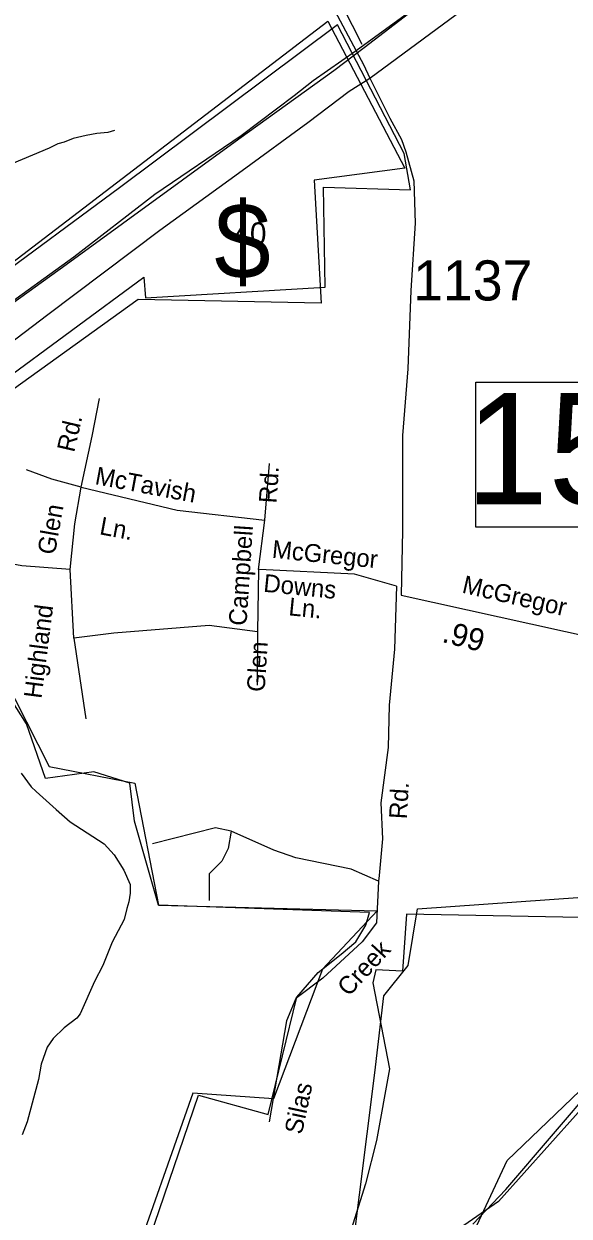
# Model space of a CAD drawing. Extents: x 1551653 to 1702041, y 811336 to 920032.
# Drawn here: x 1597078 to 1599087, y 836287 to 840677 of the extents above; entities that cross this region are included whole.
import ezdxf

# ---------------------------------------------------------------- set-up
doc = ezdxf.new("R2010")
doc.units = 0
for name, color, linetype in [('Old_Level_10', 7, 'Continuous'), ('Old_Level_11', 7, 'Continuous'), ('Old_Level_17', 7, 'Continuous'), ('Old_Level_27', 7, 'Continuous'), ('Old_Level_3', 7, 'Continuous'), ('Old_Level_31', 7, 'Continuous'), ('Old_Level_32', 7, 'Continuous'), ('Old_Level_35', 7, 'Continuous'), ('Old_Level_48', 7, 'Continuous'), ('Old_Level_49', 7, 'Continuous'), ('Old_Level_5', 7, 'Continuous'), ('Old_Level_50', 7, 'Continuous'), ('Old_Level_59', 7, 'Continuous'), ('Old_Level_62', 7, 'Continuous'), ('Old_Level_8', 7, 'Continuous')]:
    doc.layers.add(name, color=color, linetype=linetype)

msp = doc.modelspace()

# ---------------------------------------------------------------- linework, layer by layer
at = {"layer": 'Old_Level_27'}
for points in [[(1603749.199, 844559.05), (1603350.936, 844269.724), (1602985.407, 844007.693), (1602205.248, 843461.795), (1601812.441, 843177.929), (1600912.848, 842516.121), (1600254.489, 842037.883), (1599906.488, 841775.814), (1599790.188, 841685.644), (1598872.668, 840996.696), (1598523.52, 840738.735), (1598301.991, 840577.574)], [(1598352.903, 840476.76), (1598647.546, 840694.656), (1598988.5, 840943.574), (1599440.96, 841276.179), (1599818.792, 841557.187)], [(1598301.991, 840577.574), (1598143.564, 840466.869), (1598074.406, 840412.629), (1597878.626, 840264.575), (1597560.758, 840048.849), (1597262.333, 839818.275), (1596982.399, 839616.43), (1596687.022, 839400.03), (1596364.732, 839161.912), (1596107.627, 838970.645), (1596042.383, 838935.89)], [(1596092.911, 838801.101), (1596244.861, 838917.73), (1596486.859, 839105.695), (1596847.309, 839365.195), (1597165.963, 839607.175), (1597579.315, 839916.898), (1597882.302, 840136.824), (1598123.963, 840313.537), (1598276.244, 840429.627), (1598352.903, 840476.76)]]:
    msp.add_lwpolyline(points, dxfattribs=at)
at = {"layer": 'Old_Level_3'}
for points in [[(1598325.033, 840600.719), (1598253.118, 840740.824), (1598180.949, 840880.805), (1598108.584, 841020.691), (1598036.082, 841160.509), (1597963.5, 841300.289), (1597890.896, 841440.059), (1597818.33, 841579.846), (1597745.858, 841719.68), (1597673.539, 841859.588), (1597601.432, 841999.598), (1597529.593, 842139.741), (1597458.083, 842280.042), (1597386.958, 842420.531), (1597316.278, 842561.235), (1597246.098, 842702.184), (1597176.48, 842843.406), (1597107.019, 842984.781)], [(1599820.273, 841684.214), (1599709.545, 841598.913), (1599489.729, 841446.354), (1599029.592, 841109.248), (1598642.454, 840827.917), (1598331.595, 840589.236)], [(1598331.595, 840589.236), (1598220.046, 840503.935), (1597869.817, 840252.951), (1597234.156, 839790.353), (1596609.157, 839340.879), (1596036.652, 838929.135), (1595602.762, 838614.175), (1595303.386, 838389.438), (1594958.078, 838135.993), (1594733.341, 837966.21), (1594619.332, 837875.987), (1594420.841, 837711.125)]]:
    msp.add_lwpolyline(points, dxfattribs=at)
at = {"layer": 'Old_Level_31'}
for p, q in [((1598329.485, 840527.997), (1598329.485, 840527.997)), ((1598276.244, 840429.627), (1598276.244, 840429.627))]:
    msp.add_line(p, q, dxfattribs=at)
msp.add_lwpolyline([(1598743.706, 839357.959), (1599729.662, 839357.959), (1599729.662, 838823.21), (1598743.706, 838823.21), (1598743.706, 839357.959)], dxfattribs=at)
at = {"layer": 'Old_Level_32'}
for points in [[(1597987.228, 843606.896), (1597894.988, 843361.143), (1597859.075, 843253.102), (1597810.548, 843134.213), (1597782.802, 843038.921), (1597771.621, 842971.11), (1597766.982, 842831.327), (1597764.587, 842703.302), (1597759.341, 842533.512), (1597761.595, 842437.413), (1597768.458, 842371.439), (1597791.93, 842240.8), (1597800.122, 842146.869), (1597827.563, 841901.575), (1597863.79, 841596.07), (1597865.276, 841560.692), (1597884.164, 841505.608), (1597917.537, 841355.741), (1597940.118, 841294.755), (1598019.037, 841130.037), (1598087.886, 840990.068), (1598233.756, 840706.175), (1598301.991, 840577.574)], [(1598301.991, 840577.574), (1598329.485, 840527.997), (1598352.903, 840476.76)], [(1598352.903, 840476.76), (1598426.841, 840329.426), (1598469.519, 840251.188), (1598485.184, 840205.54), (1598515.592, 840099.023), (1598519.393, 839943.052), (1598504.189, 839695.78), (1598492.786, 839406.662), (1598473.781, 839161.035), (1598473.912, 838811.655), (1598467.871, 838573.462)], [(1598467.871, 838573.462), (1599190.984, 838413.375), (1599712.283, 838300.454), (1600672.675, 838162.793), (1600909.768, 838111.756), (1601019.889, 838072.308), (1601634.794, 837815.315)]]:
    msp.add_lwpolyline(points, dxfattribs=at)
at = {"layer": 'Old_Level_35'}
for p, q in [((1597966.132, 838849.406), (1597982.964, 839058.294)), ((1597942.566, 838667.472), (1597966.132, 838849.406)), ((1597262.528, 838414.784), (1597249.062, 838667.472)), ((1597942.566, 838667.472), (1597939.2, 838438.369)), ((1597262.528, 838414.784), (1597306.292, 838118.298)), ((1597939.2, 838438.369), (1597937.981, 838242.181))]:
    msp.add_line(p, q, dxfattribs=at)
for points in [[(1597289.46, 838970.696), (1597329.858, 839159.37), (1597356.79, 839297.505)], [(1597289.46, 838970.696), (1597181.731, 839001.019), (1597087.468, 839034.71)], [(1597249.062, 838667.472), (1597265.894, 838835.929), (1597289.46, 838970.696)], [(1597289.46, 838970.696), (1597642.945, 838886.467), (1597966.132, 838849.406)], [(1597249.062, 838667.472), (1597070.635, 838680.949), (1596925.875, 838707.901), (1596821.512, 838751.701), (1596703.684, 838862.883)], [(1598451.106, 838606.23), (1598296.051, 838650.626), (1597945.933, 838667.472)], [(1598451.106, 838606.23), (1598443.505, 838374.175), (1598424.5, 838168.749), (1598420.699, 838012.777), (1598393.077, 837808.614), (1598399.402, 837676.613), (1598387.64, 837540.773), (1598384.715, 837519.503)], [(1597939.2, 838438.369), (1597760.773, 838461.953), (1597410.163, 838433.055), (1597262.528, 838414.784)], [(1597842.473, 837704.379), (1597784.344, 837716.014), (1597551.829, 837657.84)], [(1597842.473, 837704.379), (1597830.848, 837640.387), (1597807.596, 837593.848), (1597761.093, 837547.308), (1597761.093, 837448.412)], [(1598384.715, 837519.503), (1598284.252, 837564.761), (1598080.801, 837605.482), (1597999.421, 837634.569), (1597842.473, 837704.379)], [(1598384.715, 837519.503), (1598377.258, 837366.968), (1598324.942, 837297.159), (1598179.62, 837163.358), (1598080.801, 837087.732), (1598045.924, 837006.287), (1597981.983, 836633.972)]]:
    msp.add_lwpolyline(points, dxfattribs=at)
at = {"layer": 'Old_Level_48'}
for points in [[(1595336.25, 840795.237), (1595562.607, 840330.789), (1595729.218, 839791.131), (1595925.632, 839311.585), (1595986.585, 838996.672), (1598198.431, 840687.572), (1598481.8, 840145.534), (1598148.053, 840101.415), (1598173.811, 839648.639), (1597499.005, 839661.558), (1596406.807, 838877.933), (1596738.766, 838471.286), (1596783.574, 838263.901), (1597003.987, 838271.184), (1597171.86, 837941.895), (1597487.463, 837881.414), (1597574.756, 837431.162), (1598380.549, 837411.001), (1598179.101, 837195.956), (1597997.798, 836718.823), (1597700.197, 836739.845), (1597460.907, 836059.147)], [(1598286.54, 836140.888), (1598371.629, 836814), (1598404.195, 837098.214), (1598494.703, 837209.396), (1598528.277, 837417.722), (1599136.932, 837461.375), (1599153.24, 838523.649), (1599889.216, 838356.267), (1600805.842, 838222.361), (1601482.103, 837944.974)], [(1601482.103, 837944.974), (1601318.378, 837447.056), (1601009.819, 837453.358), (1600830.254, 837833.203), (1600638.29, 837837.827), (1600644.586, 837421.844), (1601268.001, 837377.725), (1601154.653, 836671.816), (1601153.758, 835905.794), (1600862.935, 835913.992), (1600683.822, 835913.992), (1600487.971, 835757.991), (1600191.781, 835722.36), (1599770.54, 835724.238), (1599788.254, 836450.839), (1599394.503, 836436.576), (1599394.503, 836974.19), (1598827.554, 836340.312), (1598699.931, 836251.981), (1598681.039, 836188.954), (1598615.875, 835866.624), (1598575.282, 835630.155)]]:
    msp.add_lwpolyline(points, dxfattribs=at)
at = {"layer": 'Old_Level_49'}
for points in [[(1596452.202, 838958.392), (1597520.287, 839744.539), (1597525.949, 839668.09), (1598188.362, 839707.73), (1598182.7, 840075.821), (1598502.798, 840066.37), (1598480.019, 840199.282), (1598233.238, 840673.969), (1597430.072, 840073.754), (1596459.126, 839356.78)], [(1601442.075, 837944.358), (1600902.862, 838162.586), (1599718.108, 838345.104), (1599516.322, 838369.717), (1599166.887, 838468.173), (1599191.495, 837385.169), (1598488.673, 837398.978), (1598473.479, 837188.758), (1598374.724, 837193.824), (1598364.595, 837145.702), (1598425.367, 836829.106), (1598377.449, 836564.612), (1598336.934, 836405.048), (1598250.839, 836131.51)], [(1597488.456, 836048.39), (1597721.488, 836731.585), (1597978.532, 836660.66), (1598083.802, 837092.488), (1598162.651, 837183.567), (1598247.011, 837251.719), (1598301.358, 837297.154), (1598337.859, 837358.004), (1598351.65, 837405.062), (1597574.756, 837431.162), (1597485.97, 837740.502), (1597468.913, 837881.247), (1597336.433, 837922.899), (1597157.638, 837898.307), (1597087.469, 838099.9), (1596995.467, 838245.721)], [(1598732.617, 836257.092), (1598854.174, 836384.912), (1599359.102, 836974.128), (1599371.57, 836453.497), (1599758.058, 836422.322), (1599730.006, 835733.344)]]:
    msp.add_lwpolyline(points, dxfattribs=at)
at = {"layer": 'Old_Level_50'}
msp.add_line((1598321.663, 840530.184), (1598321.663, 840530.184), dxfattribs=at)
at = {"layer": 'Old_Level_59'}
msp.add_lwpolyline([(1598704.665, 836159.797), (1598859.582, 836491.469), (1599365.65, 836976.93)], dxfattribs=at)
at = {"layer": 'Old_Level_62'}
for points in [[(1597411.606, 840284.625), (1597387.513, 840276.986), (1597347.528, 840273.5), (1597307.44, 840266.068), (1597259.253, 840254.738), (1597227.162, 840241.205), (1597203.068, 840235.566), (1597170.875, 840219.982), (1596909.536, 840109.664), (1596814.7, 840047.02), (1596788.556, 840033.384), (1596772.356, 840021.594), (1596695.359, 839944.699), (1596604.521, 839879.955), (1596499.535, 839797.472), (1596470.93, 839757.846), (1596450.117, 839705.096), (1596440.172, 839694.28), (1596407.774, 839666.751), (1596378.554, 839641.325), (1596350.667, 839623.485), (1596321.96, 839611.49), (1596295.713, 839598.674)], [(1597067.529, 837917.965), (1597104.848, 837867.419), (1597123.713, 837850.502), (1597197.635, 837784.168), (1597248.385, 837739.159), (1597373.774, 837657.753), (1597411.196, 837617.205), (1597446.465, 837560.764), (1597469.739, 837508.425), (1597469.226, 837476.437), (1597464.817, 837444.499), (1597457.641, 837420.047), (1597447.388, 837379.293), (1597404.019, 837295.273), (1597369.366, 837208.946), (1597338.915, 837150.352), (1597285.294, 837031.114), (1597273.094, 837015.274), (1597226.649, 836979.954), (1597186.152, 836940.533), (1597163.698, 836908.801), (1597142.373, 836845.747), (1597132.12, 836789.307), (1597089.982, 836633.928), (1597071.322, 836586.203)]]:
    msp.add_lwpolyline(points, dxfattribs=at)

# ---------------------------------------------------------------- texts
at = {"layer": 'Old_Level_10'}
for s, rotation, p in [('Rd.', 76.951419, (1597263.234, 839096.604)), ('McTavish', 349.386747, (1597337.157, 838982.576)), ('Rd.', 86.228361, (1598009.191, 838910.149)), ('Glen', 79.9122, (1597192.12, 838719.316)), ('Ln.', 349.386747, (1597354.016, 838797.991)), ('Campbell', 86.228347, (1597898.138, 838459.109)), ('McGregor', 354.288122, (1597990.462, 838710.979)), ('Downs', 354.288122, (1597958.863, 838586.213)), ('Highland', 82.773431, (1597142.83, 838190.422)), ('Ln.', 354.288122, (1598051.525, 838499.339)), ('Glen', 86.228347, (1597965.012, 838215.54)), ('Rd.', 86.545197, (1598488.914, 837747.353)), ('Creek', 47.347322, (1598275.185, 837092.324)), ('Silas', 77.861972, (1598102.2, 836584.429))]:
    msp.add_text(s, height=65.6167, rotation=rotation, dxfattribs=at).set_placement(p)
at = {"layer": 'Old_Level_11'}
msp.add_text('McGregor', height=65.6167, rotation=347.042419, dxfattribs=at).set_placement((1598689.504, 838582.979))
at = {"layer": 'Old_Level_17'}
msp.add_text('.99', height=82.0208, rotation=345.390486, dxfattribs=at).set_placement((1598615.357, 838401.875))
at = {"layer": 'Old_Level_31'}
msp.add_text('152', height=410.1042, dxfattribs=at).set_placement((1598705.798, 838907.604))
at = {"layer": 'Old_Level_5'}
for s, height, p in [('$', 278.871, (1597780.082, 839738.509)), ('40', 82.0208, (1597850.054, 839863.988))]:
    msp.add_text(s, height=height, dxfattribs=at).set_placement(p)
at = {"layer": 'Old_Level_8'}
msp.add_text('1137', height=147.6375, dxfattribs=at).set_placement((1598512.652, 839658.509))

doc.saveas('drawing.dxf')
